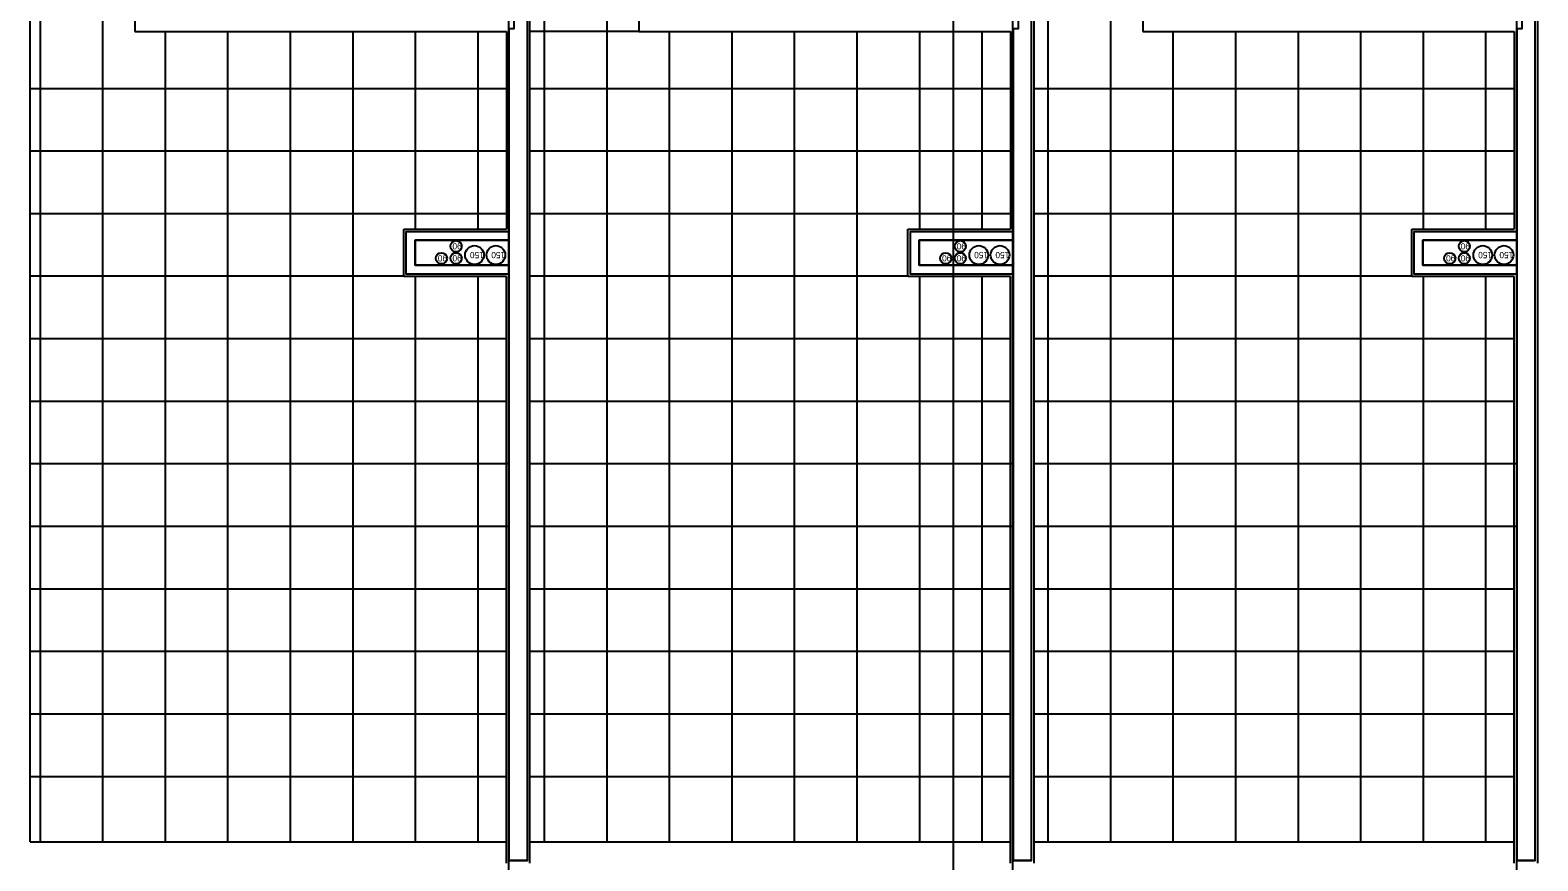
# Model space of a CAD drawing. Extents: x 1278 to 1356, y -253.7 to -224.
# Drawn here: x 1299.58 to 1311.64, y -243.76 to -237.12 of the extents above; entities that cross this region are included whole.
import ezdxf

# ---------------------------------------------------------------- set-up
doc = ezdxf.new("R2010")
doc.units = 0
for name, color, linetype in [('corte', 7, 'Continuous'), ('estereoctomias', 7, 'Continuous'), ('estrutura-eixos', 7, 'Continuous'), ('Level 1', 7, 'Continuous'), ('Level 2', 7, 'Continuous'), ('Level 21', 7, 'Continuous'), ('Level 41', 7, 'Continuous'), ('Level 59', 7, 'Continuous'), ('revestimentos', 7, 'Continuous'), ('vista', 7, 'Continuous')]:
    doc.layers.add(name, color=color, linetype=linetype)

msp = doc.modelspace()

# ---------------------------------------------------------------- linework, layer by layer
at = {"layer": 'corte'}
for p, q in [((1302.59, -239.066), (1302.59, -238.726)), ((1302.59, -238.726), (1303.41, -238.726)), ((1302.66, -238.996), (1302.66, -238.796)), ((1302.66, -238.796), (1303.41, -238.796)), ((1306.621, -239.066), (1306.621, -238.726)), ((1306.621, -238.726), (1307.441, -238.726)), ((1306.691, -238.996), (1306.691, -238.796)), ((1306.691, -238.796), (1307.441, -238.796)), ((1310.649, -239.066), (1310.649, -238.726)), ((1310.649, -238.726), (1311.469, -238.726)), ((1310.719, -238.996), (1310.719, -238.796)), ((1310.719, -238.796), (1311.469, -238.796)), ((1303.41, -238.996), (1302.66, -238.996)), ((1307.441, -238.996), (1306.691, -238.996)), ((1311.469, -238.996), (1310.719, -238.996)), ((1303.41, -239.066), (1302.59, -239.066)), ((1307.441, -239.066), (1306.621, -239.066)), ((1311.469, -239.066), (1310.649, -239.066)), ((1303.558, -243.754), (1303.41, -243.754)), ((1307.589, -243.754), (1307.441, -243.754)), ((1311.617, -243.754), (1311.469, -243.754))]:
    msp.add_line(p, q, dxfattribs=at)
at = {"layer": 'estereoctomias'}
for points in [[(1303.558, -232.094), (1303.41, -232.094), (1303.41, -234.805), (1303.45, -234.805), (1303.45, -237.106), (1303.41, -237.106), (1303.41, -243.754), (1303.558, -243.754)], [(1307.589, -232.094), (1307.441, -232.094), (1307.441, -234.805), (1307.481, -234.805), (1307.481, -237.106), (1307.441, -237.106), (1307.441, -243.754), (1307.589, -243.754)], [(1311.617, -232.094), (1311.469, -232.094), (1311.469, -234.805), (1311.509, -234.805), (1311.509, -237.106), (1311.469, -237.106), (1311.469, -243.754), (1311.617, -243.754)], [(1303.41, -239.066), (1302.59, -239.066), (1302.59, -238.726), (1303.41, -238.726), (1303.41, -238.796), (1302.66, -238.796), (1302.66, -238.996), (1303.41, -238.996)], [(1307.441, -239.066), (1306.621, -239.066), (1306.621, -238.726), (1307.441, -238.726), (1307.441, -238.796), (1306.691, -238.796), (1306.691, -238.996), (1307.441, -238.996)], [(1311.469, -239.066), (1310.649, -239.066), (1310.649, -238.726), (1311.469, -238.726), (1311.469, -238.796), (1310.719, -238.796), (1310.719, -238.996), (1311.469, -238.996)]]:
    msp.add_lwpolyline(points, close=True, dxfattribs=at)
at = {"layer": 'estrutura-eixos'}
for p, q in [((1303.409, -250.792), (1303.409, -229.609)), ((1307.439, -250.792), (1307.439, -229.62)), ((1311.469, -250.792), (1311.469, -229.62))]:
    msp.add_line(p, q, dxfattribs=at)
at = {"layer": 'Level 1'}
for p, q in [((1303.558, -243.754), (1303.558, -232.094)), ((1307.589, -243.754), (1307.589, -232.094)), ((1311.617, -243.754), (1311.617, -232.094)), ((1303.409, -243.754), (1303.409, -237.106)), ((1307.441, -243.754), (1307.441, -237.106)), ((1311.469, -243.754), (1311.469, -237.106))]:
    msp.add_line(p, q, dxfattribs=at)
at = {"layer": 'Level 2'}
for p, q in [((1311.469, -238.796), (1311.469, -238.996)), ((1299.582, -243.604), (1303.39, -243.604)), ((1303.578, -243.604), (1307.421, -243.604)), ((1307.609, -243.604), (1311.449, -243.604))]:
    msp.add_line(p, q, dxfattribs=at)
at = {"layer": 'Level 21'}
for p, q in [((1299.664, -243.604), (1299.664, -232.244)), ((1300.164, -243.604), (1300.164, -232.244)), ((1303.695, -243.604), (1303.695, -232.244)), ((1304.195, -243.604), (1304.195, -232.244)), ((1307.723, -243.604), (1307.723, -232.244)), ((1308.223, -243.604), (1308.223, -232.244)), ((1300.664, -243.604), (1300.664, -237.126)), ((1301.164, -243.604), (1301.164, -237.126)), ((1301.664, -243.604), (1301.664, -237.126)), ((1302.164, -243.604), (1302.164, -237.126)), ((1302.664, -238.706), (1302.664, -237.126)), ((1303.164, -238.706), (1303.164, -237.126)), ((1304.448, -237.126), (1303.578, -237.126)), ((1304.695, -243.604), (1304.695, -237.126)), ((1305.195, -243.604), (1305.195, -237.126)), ((1305.695, -243.604), (1305.695, -237.126)), ((1306.195, -243.604), (1306.195, -237.126)), ((1306.695, -238.706), (1306.695, -237.126)), ((1307.195, -238.706), (1307.195, -237.126)), ((1308.723, -243.604), (1308.723, -237.126)), ((1309.223, -243.604), (1309.223, -237.126)), ((1309.723, -243.604), (1309.723, -237.126)), ((1310.223, -243.604), (1310.223, -237.126)), ((1310.723, -238.706), (1310.723, -237.126)), ((1311.223, -238.706), (1311.223, -237.126)), ((1303.39, -237.584), (1299.582, -237.584)), ((1307.421, -237.584), (1303.578, -237.584)), ((1311.449, -237.584), (1307.609, -237.584)), ((1303.39, -238.084), (1299.582, -238.084)), ((1307.421, -238.084), (1303.578, -238.084)), ((1311.449, -238.084), (1307.609, -238.084)), ((1303.39, -238.584), (1299.582, -238.584)), ((1307.421, -238.584), (1303.578, -238.584)), ((1311.449, -238.584), (1307.609, -238.584)), ((1302.57, -239.084), (1299.582, -239.084)), ((1302.664, -243.604), (1302.664, -239.086)), ((1303.164, -243.604), (1303.164, -239.086)), ((1306.599, -239.084), (1303.578, -239.084)), ((1306.695, -243.604), (1306.695, -239.086)), ((1307.195, -243.604), (1307.195, -239.086)), ((1310.629, -239.084), (1307.609, -239.084)), ((1310.723, -243.604), (1310.723, -239.086)), ((1311.223, -243.604), (1311.223, -239.086)), ((1303.39, -239.584), (1299.582, -239.584)), ((1307.421, -239.584), (1303.578, -239.584)), ((1311.449, -239.584), (1307.609, -239.584)), ((1303.39, -240.084), (1299.582, -240.084)), ((1307.421, -240.084), (1303.578, -240.084)), ((1311.449, -240.084), (1307.609, -240.084)), ((1303.41, -240.584), (1299.582, -240.584)), ((1307.441, -240.584), (1303.578, -240.584)), ((1311.469, -240.584), (1307.609, -240.584)), ((1303.41, -241.084), (1299.582, -241.084)), ((1307.441, -241.084), (1303.578, -241.084)), ((1311.469, -241.084), (1307.609, -241.084)), ((1303.39, -241.584), (1299.582, -241.584)), ((1307.421, -241.584), (1303.578, -241.584)), ((1311.449, -241.584), (1307.609, -241.584)), ((1303.39, -242.084), (1299.582, -242.084)), ((1307.421, -242.084), (1303.578, -242.084)), ((1311.449, -242.084), (1307.609, -242.084)), ((1303.39, -242.584), (1299.582, -242.584)), ((1307.421, -242.584), (1303.578, -242.584)), ((1311.449, -242.584), (1307.609, -242.584)), ((1303.39, -243.084), (1299.582, -243.084)), ((1307.421, -243.084), (1303.578, -243.084)), ((1311.449, -243.084), (1307.609, -243.084))]:
    msp.add_line(p, q, dxfattribs=at)
at = {"layer": 'Level 41'}
for centre, radius in [((1302.988, -238.844), 0.045), ((1307.02, -238.844), 0.045), ((1311.05, -238.844), 0.045), ((1302.871, -238.94), 0.045), ((1302.988, -238.94), 0.045), ((1303.135, -238.914), 0.075), ((1303.306, -238.914), 0.075), ((1306.903, -238.94), 0.045), ((1307.02, -238.94), 0.045), ((1307.167, -238.914), 0.075), ((1307.337, -238.914), 0.075), ((1310.933, -238.94), 0.045), ((1311.05, -238.94), 0.045), ((1311.197, -238.914), 0.075), ((1311.367, -238.914), 0.075)]:
    msp.add_circle(centre, radius, dxfattribs=at)
at = {"layer": 'Level 59'}
msp.add_lwpolyline([(1312.108, -244.886), (1306.965, -244.886), (1306.965, -231.008), (1312.108, -231.008)], close=True, dxfattribs=at)
at = {"layer": 'revestimentos'}
for p, q in [((1303.578, -243.774), (1303.578, -232.074)), ((1307.609, -243.774), (1307.609, -232.074)), ((1311.637, -243.774), (1311.637, -232.074)), ((1300.419, -236.755), (1300.419, -237.126)), ((1304.45, -236.755), (1304.45, -237.126)), ((1308.478, -236.755), (1308.478, -237.126)), ((1300.419, -237.126), (1303.39, -237.126)), ((1303.39, -237.126), (1303.39, -238.706)), ((1304.45, -237.126), (1307.421, -237.126)), ((1307.421, -237.126), (1307.421, -238.706)), ((1308.478, -237.126), (1311.449, -237.126)), ((1311.449, -237.126), (1311.449, -238.706)), ((1302.57, -239.086), (1302.57, -238.706)), ((1302.57, -238.706), (1303.39, -238.706)), ((1306.601, -239.086), (1306.601, -238.706)), ((1306.601, -238.706), (1307.421, -238.706)), ((1310.629, -239.086), (1310.629, -238.706)), ((1310.629, -238.706), (1311.449, -238.706)), ((1303.39, -239.086), (1302.57, -239.086)), ((1303.39, -243.774), (1303.39, -239.086)), ((1307.421, -239.086), (1306.601, -239.086)), ((1307.421, -243.774), (1307.421, -239.086)), ((1311.449, -239.086), (1310.629, -239.086)), ((1311.449, -243.774), (1311.449, -239.086))]:
    msp.add_line(p, q, dxfattribs=at)
at = {"layer": 'vista'}
msp.add_line((1299.582, -243.604), (1299.582, -232.244), dxfattribs=at)

# ---------------------------------------------------------------- texts
at = {"layer": 'Level 41'}
for s, p in [('90', (1303.033, -238.819)), ('90', (1307.065, -238.819)), ('90', (1311.095, -238.819)), ('90', (1302.916, -238.915)), ('90', (1303.033, -238.915)), ('150', (1303.21, -238.889)), ('150', (1303.381, -238.889)), ('90', (1306.948, -238.915)), ('90', (1307.065, -238.915)), ('150', (1307.242, -238.889)), ('150', (1307.412, -238.889)), ('90', (1310.978, -238.915)), ('90', (1311.095, -238.915)), ('150', (1311.272, -238.889)), ('150', (1311.442, -238.889))]:
    msp.add_text(s, height=0.05, rotation=180, dxfattribs=at).set_placement(p)

doc.saveas('drawing.dxf')
